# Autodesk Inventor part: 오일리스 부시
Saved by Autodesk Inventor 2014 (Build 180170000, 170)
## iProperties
Created: 2025-02
Part Number: 오일리스 부시
Material: 구리, 합금
Document SubType Name: Modeling
Designer: dg
Density: 7.58 g/cm^3
Appearance: 구리 - 새틴
Mass: 8.78868 g
Surface Area: 13.5608 cm^2
Volume: 1.15946 cm^3
Author: jhkim
Creation Date: 2025-01-06
Sending System: Autodesk Inventor 2025
Preprocessor: ST-DEVELOPER v20
Author: dg
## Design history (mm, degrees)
node "오일리스 부시1"
node "솔리드1"
node "기준1"
